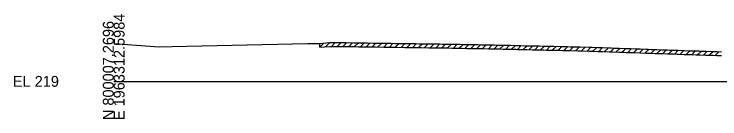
# Model space of a CAD drawing. Extents: x -26 to 1403, y -10 to 19587.
# Drawn here: x -25.7 to 156.4, y 12990.3 to 13017.4 of the extents above; entities that cross this region are included whole.
import ezdxf

# ---------------------------------------------------------------- set-up
doc = ezdxf.new("R2010")
doc.units = 0
for name, color, linetype in [('Default', 7, 'Continuous'), ('RD_GPK_XS_Cell', 7, 'Continuous'), ('RD_XS_ExGround', 7, 'Continuous'), ('RD_XS_ExPaveRet', 7, 'Continuous')]:
    doc.layers.add(name, color=color, linetype=linetype)

msp = doc.modelspace()

# ---------------------------------------------------------------- linework, layer by layer
at = {"layer": 'RD_GPK_XS_Cell'}
msp.add_line((0, 13000), (200, 13000), dxfattribs=at)
at = {"layer": 'RD_XS_ExGround'}
msp.add_lwpolyline([(0, 13009.76), (11.71, 13008.94), (15, 13009.03), (50.02, 13009.75), (53.15, 13009.81), (55.8, 13010.04), (57.25, 13010.03), (58.43, 13010.01), (59.42, 13010.01), (59.86, 13010), (62.01, 13009.97), (63.15, 13009.96), (65.01, 13009.94), (65.46, 13009.93), (66.93, 13009.91), (67.58, 13009.9), (69.72, 13009.87), (70.92, 13009.85), (71.57, 13009.84), (72.59, 13009.82), (73.16, 13009.81), (75.1, 13009.77), (76.15, 13009.76), (76.61, 13009.75), (78.07, 13009.74), (78.73, 13009.73), (79.29, 13009.72), (81.26, 13009.7), (81.61, 13009.69), (82.32, 13009.69), (83.96, 13009.66), (84.78, 13009.64), (86.28, 13009.62), (87.33, 13009.6), (87.77, 13009.6), (89.25, 13009.57), (89.89, 13009.56), (91.12, 13009.53), (92.67, 13009.51), (93.04, 13009.5), (93.83, 13009.49), (94.91, 13009.47), (95.46, 13009.46), (96.77, 13009.42), (98.25, 13009.4), (98.63, 13009.39), (99.4, 13009.38), (100.48, 13009.35), (101.03, 13009.34), (102.33, 13009.31), (103.82, 13009.28), (104.18, 13009.27), (104.91, 13009.25), (106.07, 13009.22), (106.6, 13009.21), (107.98, 13009.18), (109.39, 13009.15), (109.88, 13009.14), (110.94, 13009.11), (111.74, 13009.1), (112.18, 13009.09), (113.53, 13009.05), (115.14, 13009.02), (115.97, 13009), (117.19, 13008.97), (117.75, 13008.96), (119.71, 13008.91), (120.06, 13008.91), (120.37, 13008.9), (122.65, 13008.82), (123.47, 13008.8), (124.88, 13008.74), (126.12, 13008.71), (127.87, 13008.65), (128.34, 13008.63), (128.81, 13008.61), (130.31, 13008.56), (131.73, 13008.51), (132.23, 13008.49), (133.29, 13008.46), (134.5, 13008.42), (135.85, 13008.37), (137.3, 13008.32), (137.76, 13008.31), (138.62, 13008.27), (139.65, 13008.23), (140.1, 13008.22), (141.45, 13008.17), (142.87, 13008.12), (143.38, 13008.1), (144.46, 13008.07), (145.28, 13008.04), (145.67, 13008.03), (147.16, 13007.97), (148.45, 13007.93), (149.04, 13007.91), (150.27, 13007.87), (150.92, 13007.85), (151.24, 13007.84), (152.73, 13007.79), (154.04, 13007.74), (154.56, 13007.73), (155.56, 13007.69), (156.82, 13007.65)], dxfattribs=at)
at = {"layer": 'RD_XS_ExPaveRet'}
for p, q in [((53.15, 13008.81), (54.25, 13009.9)), ((53.15, 13008.81), (53.15, 13009.81)), ((54.65, 13008.94), (55.75, 13010.03)), ((56.15, 13009.04), (57.15, 13010.03)), ((57.65, 13009.02), (58.64, 13010.01)), ((59.15, 13009.01), (60.14, 13010)), ((60.65, 13008.99), (61.64, 13009.98)), ((62.15, 13008.97), (63.14, 13009.96)), ((63.65, 13008.95), (64.64, 13009.94)), ((65.15, 13008.94), (66.14, 13009.92)), ((66.65, 13008.91), (67.64, 13009.9)), ((68.15, 13008.89), (69.14, 13009.88)), ((69.65, 13008.87), (70.64, 13009.85)), ((71.15, 13008.84), (72.13, 13009.83)), ((72.65, 13008.82), (73.64, 13009.8)), ((74.15, 13008.79), (75.14, 13009.77)), ((75.65, 13008.76), (76.64, 13009.75)), ((77.15, 13008.75), (78.15, 13009.74)), ((78.65, 13008.73), (79.64, 13009.72)), ((80.15, 13008.71), (81.14, 13009.7)), ((81.65, 13008.69), (82.64, 13009.68)), ((83.15, 13008.67), (84.14, 13009.66)), ((84.65, 13008.65), (85.64, 13009.63)), ((86.15, 13008.62), (87.14, 13009.61)), ((53.15, 13008.81), (55.8, 13009.04)), ((53.15, 13008.81), (53.15, 13008.81)), ((55.8, 13009.04), (57.25, 13009.03)), ((57.25, 13009.03), (58.43, 13009.01)), ((58.43, 13009.01), (59.42, 13009.01)), ((59.42, 13009.01), (59.86, 13009)), ((59.86, 13009), (62.01, 13008.97)), ((62.01, 13008.97), (63.15, 13008.96)), ((63.15, 13008.96), (65.01, 13008.94)), ((65.01, 13008.94), (65.46, 13008.93)), ((65.46, 13008.93), (66.93, 13008.91)), ((66.93, 13008.91), (67.58, 13008.9)), ((67.58, 13008.9), (69.72, 13008.87)), ((69.72, 13008.87), (70.92, 13008.85)), ((70.92, 13008.85), (71.57, 13008.84)), ((71.57, 13008.84), (72.59, 13008.82)), ((72.59, 13008.82), (73.16, 13008.81)), ((73.16, 13008.81), (75.1, 13008.77)), ((75.1, 13008.77), (76.15, 13008.76)), ((76.15, 13008.76), (76.61, 13008.75)), ((76.61, 13008.75), (78.07, 13008.74)), ((78.07, 13008.74), (78.73, 13008.73)), ((78.73, 13008.73), (79.29, 13008.72)), ((79.29, 13008.72), (81.26, 13008.7)), ((81.26, 13008.7), (81.61, 13008.69)), ((81.61, 13008.69), (82.32, 13008.69)), ((82.32, 13008.69), (83.96, 13008.66)), ((83.96, 13008.66), (84.78, 13008.64)), ((84.78, 13008.64), (86.28, 13008.62)), ((86.28, 13008.62), (87.33, 13008.6)), ((87.33, 13008.6), (87.77, 13008.6)), ((87.65, 13008.6), (88.63, 13009.58)), ((87.77, 13008.6), (89.25, 13008.57)), ((89.15, 13008.57), (90.14, 13009.55)), ((89.25, 13008.57), (89.89, 13008.56)), ((89.89, 13008.56), (91.12, 13008.53)), ((90.65, 13008.54), (91.64, 13009.52)), ((91.12, 13008.53), (92.67, 13008.51)), ((92.15, 13008.52), (93.13, 13009.5)), ((92.67, 13008.51), (93.04, 13008.5)), ((93.04, 13008.5), (93.83, 13008.49)), ((93.65, 13008.49), (94.64, 13009.47)), ((93.83, 13008.49), (94.91, 13008.47)), ((94.91, 13008.47), (95.46, 13008.46)), ((95.15, 13008.46), (96.13, 13009.44)), ((95.46, 13008.46), (96.77, 13008.42)), ((96.65, 13008.43), (97.64, 13009.41)), ((96.77, 13008.42), (98.25, 13008.4)), ((98.15, 13008.4), (99.13, 13009.38)), ((98.25, 13008.4), (98.63, 13008.39)), ((98.63, 13008.39), (99.4, 13008.38)), ((99.4, 13008.38), (100.48, 13008.35)), ((99.65, 13008.37), (100.63, 13009.35)), ((100.48, 13008.35), (101.03, 13008.34)), ((101.03, 13008.34), (102.33, 13008.31)), ((101.15, 13008.34), (102.13, 13009.31)), ((102.33, 13008.31), (103.82, 13008.28)), ((102.65, 13008.3), (103.63, 13009.28)), ((103.82, 13008.28), (104.18, 13008.27)), ((104.15, 13008.27), (105.13, 13009.25)), ((104.18, 13008.27), (104.91, 13008.25)), ((104.91, 13008.25), (106.07, 13008.22)), ((105.65, 13008.23), (106.63, 13009.21)), ((106.07, 13008.22), (106.6, 13008.21)), ((106.6, 13008.21), (107.98, 13008.18)), ((107.15, 13008.2), (108.13, 13009.18)), ((107.98, 13008.18), (109.39, 13008.15)), ((108.65, 13008.17), (109.63, 13009.14)), ((109.39, 13008.15), (109.88, 13008.14)), ((109.88, 13008.14), (110.94, 13008.11)), ((110.15, 13008.13), (111.13, 13009.11)), ((110.94, 13008.11), (111.74, 13008.1)), ((111.65, 13008.1), (112.63, 13009.07)), ((111.74, 13008.1), (112.18, 13008.09)), ((112.18, 13008.09), (113.53, 13008.05)), ((113.15, 13008.06), (114.13, 13009.04)), ((113.53, 13008.05), (115.14, 13008.02)), ((114.65, 13008.03), (115.63, 13009.01)), ((115.14, 13008.02), (115.97, 13008)), ((115.97, 13008), (117.19, 13007.97)), ((116.15, 13008), (117.13, 13008.97)), ((117.19, 13007.97), (117.75, 13007.96)), ((117.65, 13007.96), (118.63, 13008.94)), ((117.75, 13007.96), (119.71, 13007.91)), ((119.15, 13007.93), (120.13, 13008.9)), ((119.71, 13007.91), (120.06, 13007.91)), ((120.06, 13007.91), (120.37, 13007.9)), ((120.37, 13007.9), (122.65, 13007.82)), ((120.65, 13007.89), (121.62, 13008.86)), ((122.15, 13007.84), (123.12, 13008.81)), ((122.65, 13007.82), (123.47, 13007.8)), ((123.47, 13007.8), (124.88, 13007.74)), ((123.65, 13007.79), (124.62, 13008.75)), ((125.15, 13007.73), (126.13, 13008.71)), ((126.65, 13007.69), (127.62, 13008.65)), ((128.15, 13007.63), (129.12, 13008.6)), ((129.65, 13007.59), (130.62, 13008.55)), ((131.15, 13007.53), (132.12, 13008.5)), ((132.65, 13007.48), (133.62, 13008.45)), ((134.15, 13007.43), (135.12, 13008.4)), ((135.65, 13007.38), (136.62, 13008.35)), ((137.15, 13007.33), (138.12, 13008.29)), ((138.65, 13007.27), (139.62, 13008.24)), ((140.15, 13007.22), (141.12, 13008.18)), ((141.65, 13007.16), (142.62, 13008.13)), ((143.15, 13007.11), (144.12, 13008.08)), ((144.65, 13007.06), (145.62, 13008.03)), ((146.15, 13007.01), (147.12, 13007.98)), ((147.65, 13006.96), (148.62, 13007.93)), ((149.15, 13006.91), (150.12, 13007.88)), ((150.65, 13006.86), (151.62, 13007.82)), ((152.15, 13006.81), (153.12, 13007.77)), ((124.88, 13007.74), (126.12, 13007.71)), ((126.12, 13007.71), (127.87, 13007.65)), ((127.87, 13007.65), (128.34, 13007.63)), ((128.34, 13007.63), (128.81, 13007.61)), ((128.81, 13007.61), (130.31, 13007.56)), ((130.31, 13007.56), (131.73, 13007.51)), ((131.73, 13007.51), (132.23, 13007.49)), ((132.23, 13007.49), (133.29, 13007.46)), ((133.29, 13007.46), (134.5, 13007.42)), ((134.5, 13007.42), (135.85, 13007.37)), ((135.85, 13007.37), (137.3, 13007.32)), ((137.3, 13007.32), (137.76, 13007.31)), ((137.76, 13007.31), (138.62, 13007.27)), ((138.62, 13007.27), (139.65, 13007.23)), ((139.65, 13007.23), (140.1, 13007.22)), ((140.1, 13007.22), (141.45, 13007.17)), ((141.45, 13007.17), (142.87, 13007.12)), ((142.87, 13007.12), (143.38, 13007.1)), ((143.38, 13007.1), (144.46, 13007.07)), ((144.46, 13007.07), (145.28, 13007.04)), ((145.28, 13007.04), (145.67, 13007.03)), ((145.67, 13007.03), (147.16, 13006.97)), ((147.16, 13006.97), (148.45, 13006.93)), ((148.45, 13006.93), (149.04, 13006.91)), ((149.04, 13006.91), (150.27, 13006.87)), ((150.27, 13006.87), (150.92, 13006.85)), ((150.92, 13006.85), (151.24, 13006.84)), ((151.24, 13006.84), (152.73, 13006.79)), ((152.73, 13006.79), (154.04, 13006.74)), ((153.65, 13006.75), (154.62, 13007.72)), ((154.04, 13006.74), (154.56, 13006.73)), ((154.56, 13006.73), (155.56, 13006.69)), ((155.15, 13006.71), (156.12, 13007.67)), ((155.56, 13006.69), (156.82, 13006.65))]:
    msp.add_line(p, q, dxfattribs=at)

# ---------------------------------------------------------------- texts
at = {"layer": 'Default'}
msp.add_text('-', height=0.0001, dxfattribs=at).set_placement((0, 13000))
at = {"layer": 'RD_GPK_XS_Cell'}
for s, p in [('E 1963312.5984', (2.8, 12990)), ('N 800007.2696', (0, 12990))]:
    msp.add_text(s, height=2.8, rotation=90, dxfattribs=at).set_placement(p)
msp.add_text('EL 219', height=2.8, dxfattribs=at).set_placement((-26, 12998.6))

doc.saveas('drawing.dxf')
